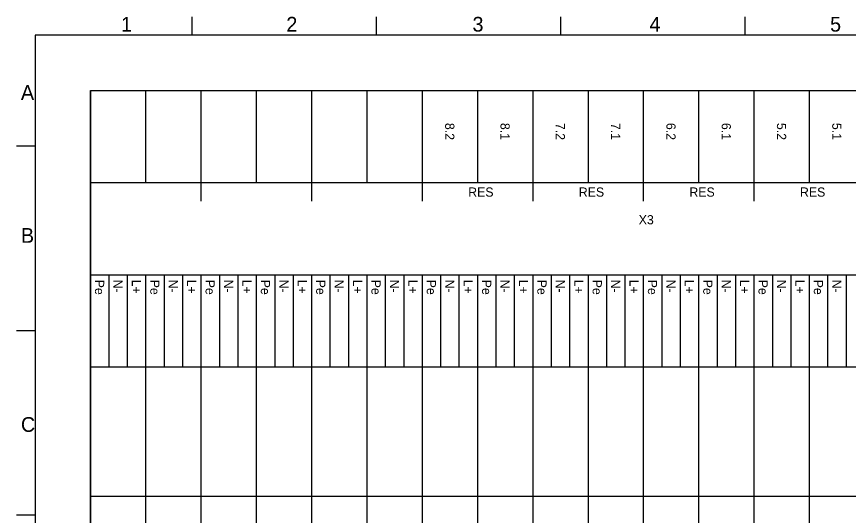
# Model space of a CAD drawing. Extents: x 0 to 395, y 0 to 270.
# Drawn here: x 0 to 225.6, y 134.9 to 270.1 of the extents above; entities that cross this region are included whole.
import ezdxf

# ---------------------------------------------------------------- set-up
doc = ezdxf.new("R2010")
doc.units = 0
for name, color, linetype in [('30_Graphik', 7, 'Continuous'), ('30_Text', 7, 'Continuous'), ('90_Plankopf', 7, 'Continuous')]:
    doc.layers.add(name, color=color, linetype=linetype)

msp = doc.modelspace()

# ---------------------------------------------------------------- linework, layer by layer
at = {"layer": '30_Graphik'}
for p, q in [((20, 40), (20, 250)), ((20, 250), (350, 250)), ((20, 250), (20, 40)), ((35, 250), (35, 225)), ((50, 250), (50, 220)), ((65, 250), (65, 225)), ((80, 250), (80, 220)), ((95, 250), (95, 225)), ((110, 250), (110, 220)), ((125, 250), (125, 225)), ((140, 250), (140, 220)), ((155, 250), (155, 225)), ((170, 250), (170, 220)), ((185, 250), (185, 225)), ((200, 250), (200, 220)), ((215, 250), (215, 225)), ((350, 225), (20, 225)), ((350, 200), (20, 200)), ((25, 200), (25, 175)), ((30, 200), (30, 175)), ((35, 200), (35, 40)), ((40, 200), (40, 175)), ((45, 200), (45, 175)), ((50, 200), (50, 40)), ((55, 200), (55, 175)), ((60, 200), (60, 175)), ((65, 200), (65, 40)), ((70, 200), (70, 175)), ((75, 200), (75, 175)), ((80, 200), (80, 40)), ((85, 200), (85, 175)), ((90, 200), (90, 175)), ((95, 200), (95, 40)), ((100, 200), (100, 175)), ((105, 200), (105, 175)), ((110, 200), (110, 40)), ((115, 200), (115, 175)), ((120, 200), (120, 175)), ((125, 200), (125, 40)), ((130, 200), (130, 175)), ((135, 200), (135, 175)), ((140, 200), (140, 40)), ((145, 200), (145, 175)), ((150, 200), (150, 175)), ((155, 200), (155, 40)), ((160, 200), (160, 175)), ((165, 200), (165, 175)), ((170, 200), (170, 40)), ((175, 200), (175, 175)), ((180, 200), (180, 175)), ((185, 200), (185, 40)), ((190, 200), (190, 175)), ((195, 200), (195, 175)), ((200, 200), (200, 40)), ((205, 200), (205, 175)), ((210, 200), (210, 175)), ((215, 200), (215, 40)), ((220, 200), (220, 175)), ((225, 200), (225, 175)), ((350, 175), (20, 175)), ((350, 140), (20, 140))]:
    msp.add_line(p, q, dxfattribs=at)
at = {"layer": '90_Plankopf'}
for p, q in [((47.5, 270), (47.5, 265)), ((97.5, 270), (97.5, 265)), ((147.5, 270), (147.5, 265)), ((197.5, 270), (197.5, 265)), ((390, 265), (5, 265)), ((5, 265), (5, 5)), ((0, 235), (5, 235)), ((0, 185), (5, 185)), ((0, 135), (5, 135))]:
    msp.add_line(p, q, dxfattribs=at)

# ---------------------------------------------------------------- texts
at = {"layer": '30_Text'}
for s, rotation, p in [('8.2', 270, (116.25, 241.25)), ('8.1', 270, (131.25, 241.25)), ('7.2', 270, (146.25, 241.25)), ('7.1', 270, (161.25, 241.25)), ('6.2', 270, (176.25, 241.25)), ('6.1', 270, (191.25, 241.25)), ('5.2', 270, (206.25, 241.25)), ('5.1', 270, (221.25, 241.25)), ('RES', 360, (122.5, 221.25)), ('RES', 360, (152.5, 221.25)), ('RES', 360, (182.5, 221.25)), ('RES', 360, (212.5, 221.25)), ('Pe', 270, (21.25, 198.75)), ('N-', 270, (26.25, 198.75)), ('L+', 270, (31.25, 198.75)), ('Pe', 270, (36.25, 198.75)), ('N-', 270, (41.25, 198.75)), ('L+', 270, (46.25, 198.75)), ('Pe', 270, (51.25, 198.75)), ('N-', 270, (56.25, 198.75)), ('L+', 270, (61.25, 198.75)), ('Pe', 270, (66.25, 198.75)), ('N-', 270, (71.25, 198.75)), ('L+', 270, (76.25, 198.75)), ('Pe', 270, (81.25, 198.75)), ('N-', 270, (86.25, 198.75)), ('L+', 270, (91.25, 198.75)), ('Pe', 270, (96.25, 198.75)), ('N-', 270, (101.25, 198.75)), ('L+', 270, (106.25, 198.75)), ('Pe', 270, (111.25, 198.75)), ('N-', 270, (116.25, 198.75)), ('L+', 270, (121.25, 198.75)), ('Pe', 270, (126.25, 198.75)), ('N-', 270, (131.25, 198.75)), ('L+', 270, (136.25, 198.75)), ('Pe', 270, (141.25, 198.75)), ('N-', 270, (146.25, 198.75)), ('L+', 270, (151.25, 198.75)), ('Pe', 270, (156.25, 198.75)), ('N-', 270, (161.25, 198.75)), ('L+', 270, (166.25, 198.75)), ('Pe', 270, (171.25, 198.75)), ('N-', 270, (176.25, 198.75)), ('L+', 270, (181.25, 198.75)), ('Pe', 270, (186.25, 198.75)), ('N-', 270, (191.25, 198.75)), ('L+', 270, (196.25, 198.75)), ('Pe', 270, (201.25, 198.75)), ('N-', 270, (206.25, 198.75)), ('L+', 270, (211.25, 198.75)), ('Pe', 270, (216.25, 198.75)), ('N-', 270, (221.25, 198.75))]:
    msp.add_text(s, height=2.5, rotation=rotation, dxfattribs=at).set_placement(p)
msp.add_text('X3', height=2.5, dxfattribs=at).set_placement((168.75, 213.75))
at = {"layer": '90_Plankopf'}
for s, p in [('1', (28.33, 266)), ('2', (73.17, 266)), ('3', (123.67, 266)), ('4', (171.67, 266)), ('5', (220.67, 266)), ('A', (1.17, 247.5)), ('B', (1.17, 208.75)), ('C', (1.17, 157.5))]:
    msp.add_text(s, height=4, dxfattribs=at).set_placement(p)

doc.saveas('drawing.dxf')
